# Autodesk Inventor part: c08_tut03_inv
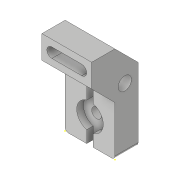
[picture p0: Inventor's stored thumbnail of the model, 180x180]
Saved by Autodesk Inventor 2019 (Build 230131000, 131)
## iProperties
Created: 2015-03
Part Number: c08_tut03_inv
Material: Generic
Document SubType Name: Modeling
Designer: Sandeep
Density: 1 g/cm^3
Appearance: Default
Author: Sandeep
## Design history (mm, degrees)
sketch "Sketch1"
  geometry: L1 (0, 0)-(0, 30); L2 (0, 30)-(-14, 44); L3 (-14, 44)-(-14, 58); L4 (-14, 58)-(0, 58); L5 (14, 44)-(14, 0); L6 (14, 0)-(0, 0); L7 (0, 58)-(14, 44)
  constraints: 14 end point, 3 parallel, 1 horizontal, 1 perpendicular, 1 vertical
  dimensions: "d0" = 14 distance between parallel lines of L5 L1; "d1" = 14 distance from line of L4.end L5; "d2" = 14 horizontal distance of L4.end L5.start; "d3" = 28 distance between parallel lines of L3 L5; "d4" = 58 distance between parallel lines of L4 L6; "d5" = 14 distance of L2.end L3.end
extrude "Extrusion1" new body sketch "Sketch1" distance "d6" = 30; taper "d7" = 0 deg
sketch "Sketch2"
  geometry: 1 further point
hole "Hole1" diameter "d10" = 8; stored, may be unused: countersink angle "d14" = 90 deg, drill point angle "d16" = 118 deg; dims "d8" = 21, "d9" = 8, "d11" = 6, "d12" = 4, "d13" = 2, "d15" = 8
sketch "Sketch3"
  geometry: L1 (0, 0)-(30, 0) reference; L2 (0, -30)-(30, -30) reference; L3 (30, 0)-(30, -30) reference; L4 (13, 0)-(13, -7.254); L5 (0, 3)-(30, 3) reference; L6 (17, 0)-(17, -7.254); L7 (15, -15)-(15, 7.075); L8 (13, 0)-(17, 0); L9 (-6.754, -15)-(33.848, -15); L10 (13, -22.746)-(13, -30); L11 (17, -30)-(17, -22.746); C1 r 3 at (15, -15); A1 r 8 centre (15, -15) between (13, -7.254) and (13, -22.746); A2 r 8 centre (15, -15) between (17, -22.746) and (17, -7.254)
  constraints: 14 end point, 5 point on line, 4 point on circle, 3 centre point, 2 parallel, 2 perpendicular, 1 coincident, 1 collinear, 1 horizontal, 1 vertical, 2 other
  dimensions: "d19" = 6 diameter of C1; "d21" = 15 distance from line of L2 A1.centre; "d22" = 15 distance from line of A1.centre L3; "d23" = 4 distance between parallel lines of L6 L4; "d24" = 4 distance between parallel lines of L11 L10; "d25" = 8 radius of A2; "d26" = 8 radius of A1
sketch "Sketch4"
  geometry: 1 further point
extrude "Extrusion2" cut sketch "Sketch3" distance "d27" = 4; taper "d28" = 0 deg
sketch "Sketch5"
  geometry: L1 (6, 7)-(24, 7); L2 (6, 4)-(24, 4); L3 (24, 10)-(6, 10); L4 (0, 14)-(30, 14) reference; L5 (30, 0)-(30, 14) reference; A1 r 3 centre (6, 7) between (6, 10) and (6, 4); A2 r 3 centre (24, 7) between (24, 4) and (24, 10); 2 further points
  constraints: 8 end point, 4 point on circle, 4 tangent, 2 centre point, 1 horizontal, 1 midpoint, 1 parallel
  dimensions: "d29" = 7 distance between parallel lines of L4 L1; "d30" = 18 distance of L1.start L1.end; "d31" = 6 distance from line of L5 L1.end; "d32" = 3 radius of A2
extrude "Extrusion3" cut sketch "Sketch5" distance "d33" = 11; taper "d34" = 0 deg
sketch "Sketch6"
  geometry: C1 r 3 at (0, 0); C2 r 3 at (0, 0) reference; 1 further point
  constraints: 1 centre point, 1 concentric
extrude "Extrusion4" cut sketch "Sketch6" distance "d35" = 35.25; taper "d36" = 0 deg
fillet "Fillet2" dims "d37" = 2
body "Solid1"
other parameters: "d20" = 16
